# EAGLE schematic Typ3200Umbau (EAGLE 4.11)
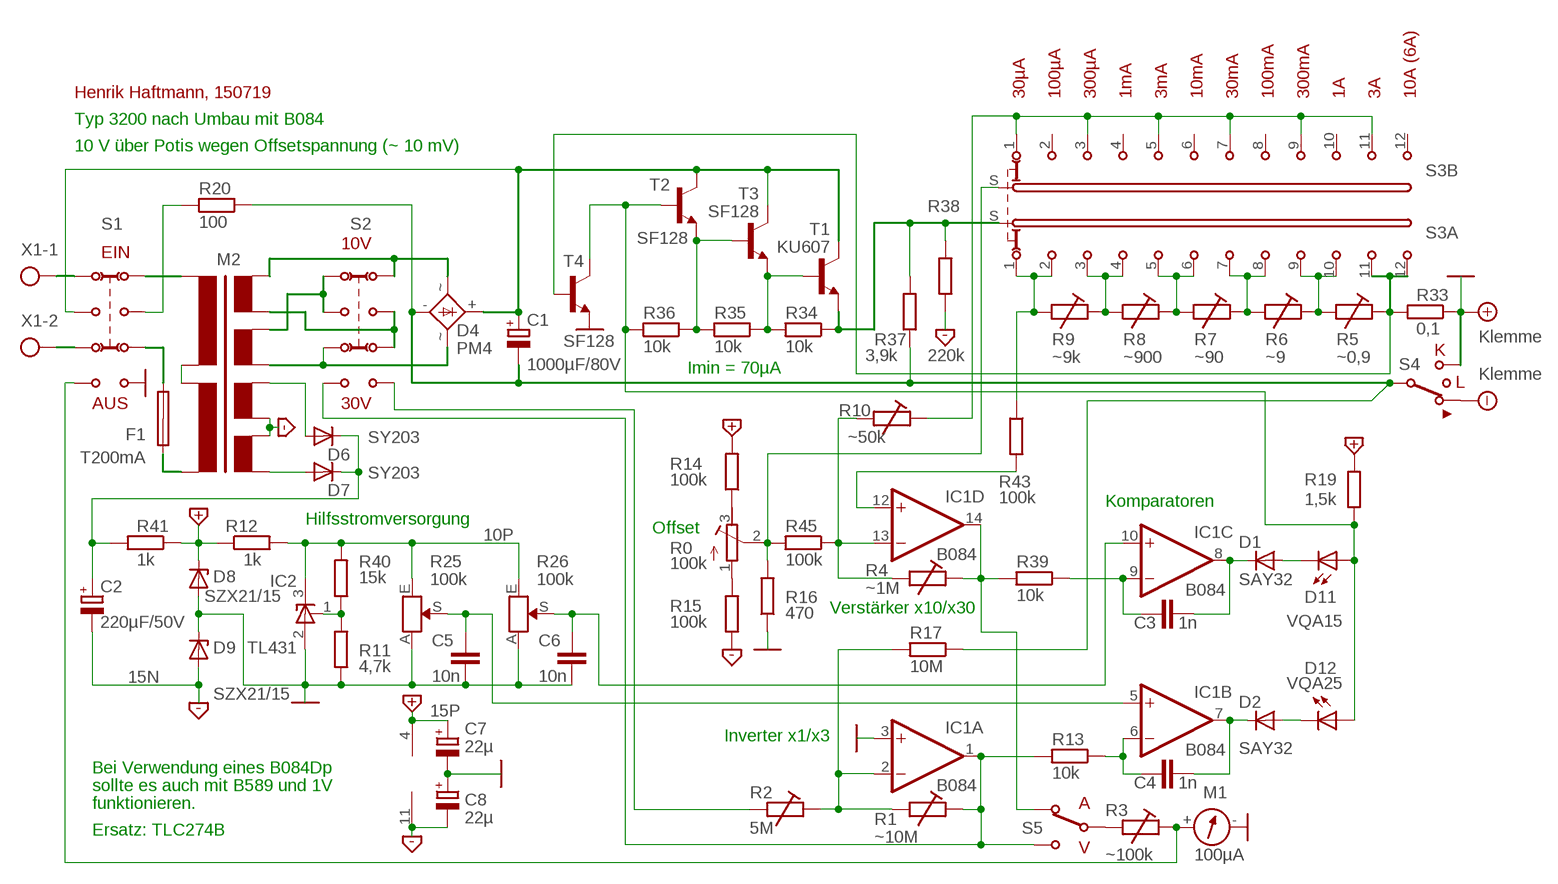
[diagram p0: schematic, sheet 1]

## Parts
C1  1000µF/80V  CPOL-EUE7.5-18  [E7,5-18]
C2  220µF/50V  CPOL-EUE7.5-18  [E7,5-18]
C3  1n  C-EU050-024X044  [C050-024X044]
C4  1n  C-EU050-024X044  [C050-024X044]
C5  10n  C-EU050-024X044  [C050-024X044]
C6  10n  C-EU050-024X044  [C050-024X044]
C7  22µ  CPOL-EUE7.5-18  [E7,5-18]
C8  22µ  CPOL-EUE7.5-18  [E7,5-18]
D1  SAY32  DIODE-D-10  [D-10]
D2  SAY32  DIODE-D-10  [D-10]
D4  PM4  FBU4  [FBU4]
D6  SY203  DIODE-D-10  [D-10]
D7  SY203  DIODE-D-10  [D-10]
D8  SZX21/15  ZENER-DIODEF126-10  [F126Z10]
D9  SZX21/15  ZENER-DIODEF126-10  [F126Z10]
D11  VQA15  LED5MM  [LED5MM]
D12  VQA25  LED5MM  [LED5MM]
F1  T200mA  SHK20L  [SHK20L]
IC1  B084  TL084P  [DIL14]
IC2  TL431  TL431CLP  [TO92-CLP]
M1  100µA  MESSWERK  [MESSWERK]
M2  TRAFO  [TRAFO]
R0  100k  R-TRIMM3304W  [RTRIM3304W]
R1  ~10M  RTRIM  [RTRIM]
R2  5M  RTRIM  [RTRIM]
R3  ~100k  RTRIM  [RTRIM]
R4  ~1M  RTRIM  [RTRIM]
R5  ~0,9  RTRIM  [RTRIM]
R6  ~9  RTRIM  [RTRIM]
R7  ~90  RTRIM  [RTRIM]
R8  ~900  RTRIM  [RTRIM]
R9  ~9k  RTRIM  [RTRIM]
R10  ~50k  RTRIM  [RTRIM]
R11  4,7k  R-EU_0207/10  [0207/10]
R12  1k  R-EU_0207/10  [0207/10]
R13  10k  R-EU_0207/10  [0207/10]
R14  100k  R-EU_0207/10  [0207/10]
R15  100k  R-EU_0207/10  [0207/10]
R16  470  R-EU_0207/10  [0207/10]
R17  10M  R-EU_0207/10  [0207/10]
R19  1,5k  R-EU_0207/10  [0207/10]
R20  100  R-EU_0207/10  [0207/10]
R25  100k  RPOT  [RPOT]
R26  100k  RPOT  [RPOT]
R33  0,1  R-EU_0207/10  [0207/10]
R34  10k  R-EU_0207/10  [0207/10]
R35  10k  R-EU_0207/10  [0207/10]
R36  10k  R-EU_0207/10  [0207/10]
R37  3,9k  R-EU_0207/10  [0207/10]
R38  220k  R-EU_0207/10  [0207/10]
R39  10k  R-EU_0207/10  [0207/10]
R40  15k  R-EU_0207/10  [0207/10]
R41  1k  R-EU_0207/10  [0207/10]
R43  100k  R-EU_0207/10  [0207/10]
R45  100k  R-EU_0207/10  [0207/10]
S1  SWITCH2N  [SWITCH2N]
S2  SWITCH2N  [SWITCH2N]
S3A  SWITCH12  [SWITCH12]
S3B  SWITCH12  [SWITCH12]
S4  U3  [U2]
S5  U2  [U2]
T1  KU607  -NPN-TO3/  [TO3]
T2  SF128  -NPN-TO18-  [TO18-]
T3  SF128  -NPN-TO18-  [TO18-]
T4  SF128  -NPN-TO18-  [TO18-]
X1  W237-102  [W237-102]

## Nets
10P: IC2.3(C) R12.2 R25.E R26.E R40.2
15N: C2.- C8.- D9.A IC1.11(P:V-) M2.10 M2.11 R15.1 R38.1
15P: C7.+ D8.C IC1.4(P:V+) R12.1 R14.2 R19.2 R41.1
40P: C2.+ D6.C D7.C R41.2
+U: C1.+ D4.+ S1.3 T1.C T2.3(C) T3.3(C)
-U: C1.- D4.- R17.1 R20.1 R37.1 S4.S
-UB: S4.S1 ; supply symbol labelled Klemme
GND: C5.1 C6.1 C7.- C8.+ D8.A D9.C IC1.3(A:+IN) IC2.2(A) M1.- R11.1 R16.1 R25.A R26.A R33.1 S1.8 S4.S2 T4.1(E) ; supply symbol labelled Klemme
N$1: R0.2(S) R16.2 R45.2 S3B.S
N$2: IC2.1(R) R11.2 R40.1
N$3: IC1.12(D:+IN) R43.2
N$4: IC1.13(D:-IN) R4.1 R10.1 R45.1
N$5: IC1.14(D:OUT) R4.2 R39.2 S5.S1
N$6: R5.2 R33.2 S3A.11 S3A.12 T4.2(B)
N$7: C5.2 IC1.5(B:+IN) R25.S
N$8: C6.2 IC1.10(C:+IN) R26.S
N$9: C3.1 IC1.9(C:-IN) R39.1
N$10: C3.2 D1.C IC1.8(C:OUT)
N$11: C4.1 IC1.6(B:-IN) R13.1
N$12: C4.2 D2.C IC1.7(B:OUT)
N$13: S1.1 X1.1
N$14: R0.3(A) R14.1
N$15: R0.1(E) R15.2
N$16: IC1.2(A:-IN) R1.1 R2.2 R17.2
N$17: R2.1 S2.8
N$18: IC1.1(A:OUT) R1.2 R13.2 S2.7 S5.S2
N$19: D1.A D11.K(C)
N$20: D11.A D12.A R19.1 R36.2 T2.2(B) T4.3(C)
N$21: D2.A D12.K(C)
N$22: M2.1 S1.2
N$23: S1.5 X1.2
N$24: F1.2A S1.6
N$25: R20.2 S1.4
N$26: M2.2 M2.3
N$27: F1.1A M2.4
N$28: M2.7 S2.1 S2.3
N$29: M2.6 S2.4 S2.6
N$30: R5.1 R6.2 S3A.9 S3A.10
N$31: R6.1 R7.2 S3A.7 S3A.8
N$32: D4.~(AC1) M2.5 S2.2
N$33: D4.~(AC2) M2.8 S2.5
N$35: R3.1 S5.S
N$36: M1.+ R3.2 S1.7
N$37: R9.1 R43.1 S3A.1 S3A.2
N$38: R8.1 R9.2 S3A.3 S3A.4
N$39: R7.1 R8.2 S3A.5 S3A.6
N$41: R35.2 R36.1 T2.1(E) T3.2(B)
N$42: R34.2 R35.1 T1.B T3.1(E)
N$45: R10.2 S3B.1 S3B.3 S3B.5 S3B.7 S3B.9 S3B.11
N$48: D6.A M2.9
N$49: D7.A M2.12
UREG: R34.1 R37.2 R38.2 S3A.S T1.E
Unconnected: F1.1B F1.2B S3B.2 S3B.4 S3B.6 S3B.8 S3B.10 S3B.12

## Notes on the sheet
- Henrik Haftmann, 150719 | 30µA | 100µA | 300µA | 1mA | 3mA | 10mA | 30mA | 100mA | 300mA | 1A | 3A | 10A (6A)
- Typ 3200 nach Umbau mit B084
- 10 V über Potis wegen Offsetspannung (~ 10 mV)
- 10V
- EIN
- K
- Imin = 70µA
- L
- AUS | 30V
- Komparatoren
- Hilfsstromversorgung
- Offset
- Verstärker x10/x30
- Inverter x1/x3
- Bei Verwendung eines B084Dp
- sollte es auch mit B589 und 1V
- funktionieren. | A
- Ersatz: TLC274B
- V

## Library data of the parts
C1 C2 C7 C8 = rcl:CPOL-EU: POLARIZED CAPACITOR, European symbol
C3-C6 = rcl:C-EU: CAPACITOR, European symbol
D1 D2 D6 D7 = diode:DIODE-: DIODE
D4 = statron:FBU4: Gleichrichter
D8 D9 = diode:ZENER-DIODE: Z-Diode
D11 D12 = led:LED: LED
F1 = fuse:SHK20L: FUSE HOLDER 5 x 20 mm, SH contact, SHH1 Schukat, E1073 Buerklin
IC1 = linear:TL084: OP AMP
IC2 = v-reg:TL431CLP: VOLTAGE REGULATOR
M1 = statron:MESSWERK
M2 = statron:TRAFO
R0 = rcl:R-TRIMM: Trimm resistor
R1-R10 = statron:RTRIM
R11-R17 R19 R20 R33-R41 R43 R45 = rcl:R-EU_: RESISTOR, European symbol
R25 R26 = statron:RPOT
S1 S2 = statron:SWITCH2N
S3A S3B = statron:SWITCH12: Drehschalter begrenzbar, DDR-Version kaskadierbar
S4 = statron:U3: Umschalter, 1-polig, mit kontaktloser Mittelstellung
S5 = statron:U2: Umschalter, 1-polig
T1-T4 = transistor:*-NPN-: NPN Transistror
X1 = con-wago-500:W237-102: WAGO SCREW CLAMP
